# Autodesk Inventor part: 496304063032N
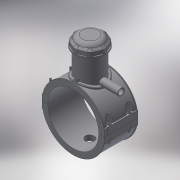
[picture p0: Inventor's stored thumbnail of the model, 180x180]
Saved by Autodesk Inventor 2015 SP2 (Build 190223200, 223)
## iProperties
Created: 2017-07
Part Number: 496304063032N
Material: Generic
Description: PLASSON TAPPING SADDLE 63x32
Document SubType Name: Modeling
Designer: KIM
Mass: 280.686 g
Surface Area: 972.201 cm^2
Volume: 280.686 cm^3
Density: 1 g/cm^3
Appearance: Default
Author: KIM
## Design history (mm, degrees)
derived "496304.ipt"
feature "Solid1::496304.ipt"
feature "Solid2::496304.ipt"
feature "Solid4::496304.ipt"
feature "Solid5::496304.ipt"
tag "TaggingFeature1"
body "Solid1"
body "Solid2"
other parameters: "d0" = 63, "d3" = 15.75, "d4" = 118, "d5" = 0, "d6" = 0.1, "d8" = 0, "d19" = 6, "d20" = 6, "d21" = 70.8, "d23" = 0, "d24" = 35.4, "d26" = 0, "d29" = 3, "d30" = 21, "d31" = 6, "d32" = 0, "d33" = 0, "d34" = 0.6, "d40" = 42.588, "d41" = 56.7, "d43" = 0, "d45" = 0, "d47" = 111.75, "d70" = 15, "d72" = 0, "d73" = 6, "d75" = 5, "d76" = 0, "d77" = 3.15, "d78" = 61.5, "d79" = 15, "d80" = 47.2, "d82" = 5 deg, "d84" = 4, "d85" = 14, "d86" = 0, "d87" = 3, "d88" = 0, "d89" = 1, "d90" = 1, "d91" = 94.4, "d92" = 0, "d93" = 0.5, "d94" = 33.15789, "d96" = 83.538, "d97" = 2.36, "d98" = 0, "d102" = 0.63, "d120" = 140 deg, "d121" = 24.228, "d122" = 20 deg, "d123" = 163.8, "d124" = 49.14, "d126" = 0, "d143" = 64.89, "d145" = 14.53846, "d149" = 0.945, "d150" = 15.99231, "d153" = 118, "d154" = 0, "d156" = 40.95, "d157" = 160 deg, "d159" = 3.78, "d161" = 0.945, "d162" = 70.8, "d163" = 0, "d164" = 31.5, "d167" = 6.3, "d168" = 39.95122, "d170" = 3.375, "d172" = 0, "d173" = 1, "d175" = 31.5, "d176" = 20 deg, "d177" = 4.41, "d178" = 18.9, "d180" = 0, "d183" = 7.56, "d184" = 3.528, "d185" = 38.35, "d186" = 38.35, "d187" = 40.95, "d188" = 5.67, "d189" = 4.41, "d190" = 0, "d191" = 61.425, "d193" = 6.3, "d194" = 4.13, "d195" = 90 deg, "d197" = 0, "d199" = 0, "d200" = 9.45, "d202" = 0, "d204" = 53.865, "d205" = 39.69, "d206" = 48.195, "d207" = 67.5, "d208" = 70.2, "d209" = 83.7, "d210" = 48.762, "d211" = 56.7, "d212" = 45.36, "d213" = -3.6, "d216" = 0, "d217" = 6.3, "d218" = 6.3, "d219" = 1.26, "d222" = 63, "d224" = 0, "d230" = 3.78, "d233" = 6, "d237" = 35.4, "d238" = 6.02433, "d240" = 35.4, "d241" = 35.4, "d242" = 35.4, "d243" = 6, "d244" = 35.4, "d245" = 35.4, "d246" = 35.4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
